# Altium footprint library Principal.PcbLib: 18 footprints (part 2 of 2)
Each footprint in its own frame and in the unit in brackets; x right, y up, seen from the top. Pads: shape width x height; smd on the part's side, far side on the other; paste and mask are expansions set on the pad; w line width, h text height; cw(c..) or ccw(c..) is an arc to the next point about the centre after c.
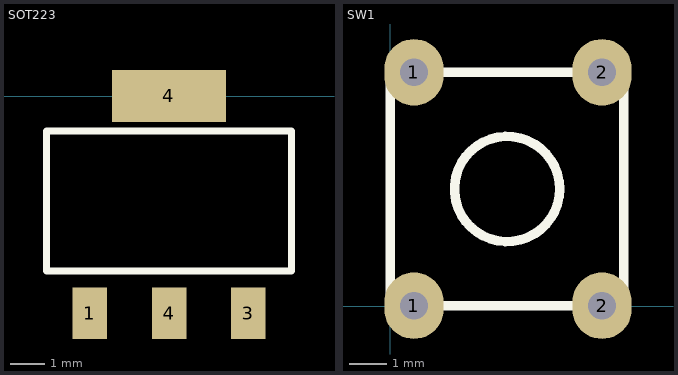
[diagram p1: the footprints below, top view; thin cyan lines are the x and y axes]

## SOT223 [mm]
pads (4):
  rect 1x1.5 smd: 1(3.788,-6.292) 3(8.388,-6.292) 4(6.088,-6.292)
  rect 3.3x1.5 smd: 4(6.084,0.008)
Top Overlay:
  lines w0.2: 2.528,-5.072 9.64,-5.072 9.64,-1.008 2.528,-1.008 2.528,-5.072

## SW1 [mm]
pads (4):
  oval 1.6x1.8 hole 0.75: 1(0.635,0.012) 1(0.635,6.312) 2(5.715,0.012) 2(5.715,6.312)
Top Overlay:
  circle w0.254: c3.15,3.162 r1.42
  lines w0.254: 0,0.012 0,6.312 6.3,6.312 6.3,0.012 0,0.012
